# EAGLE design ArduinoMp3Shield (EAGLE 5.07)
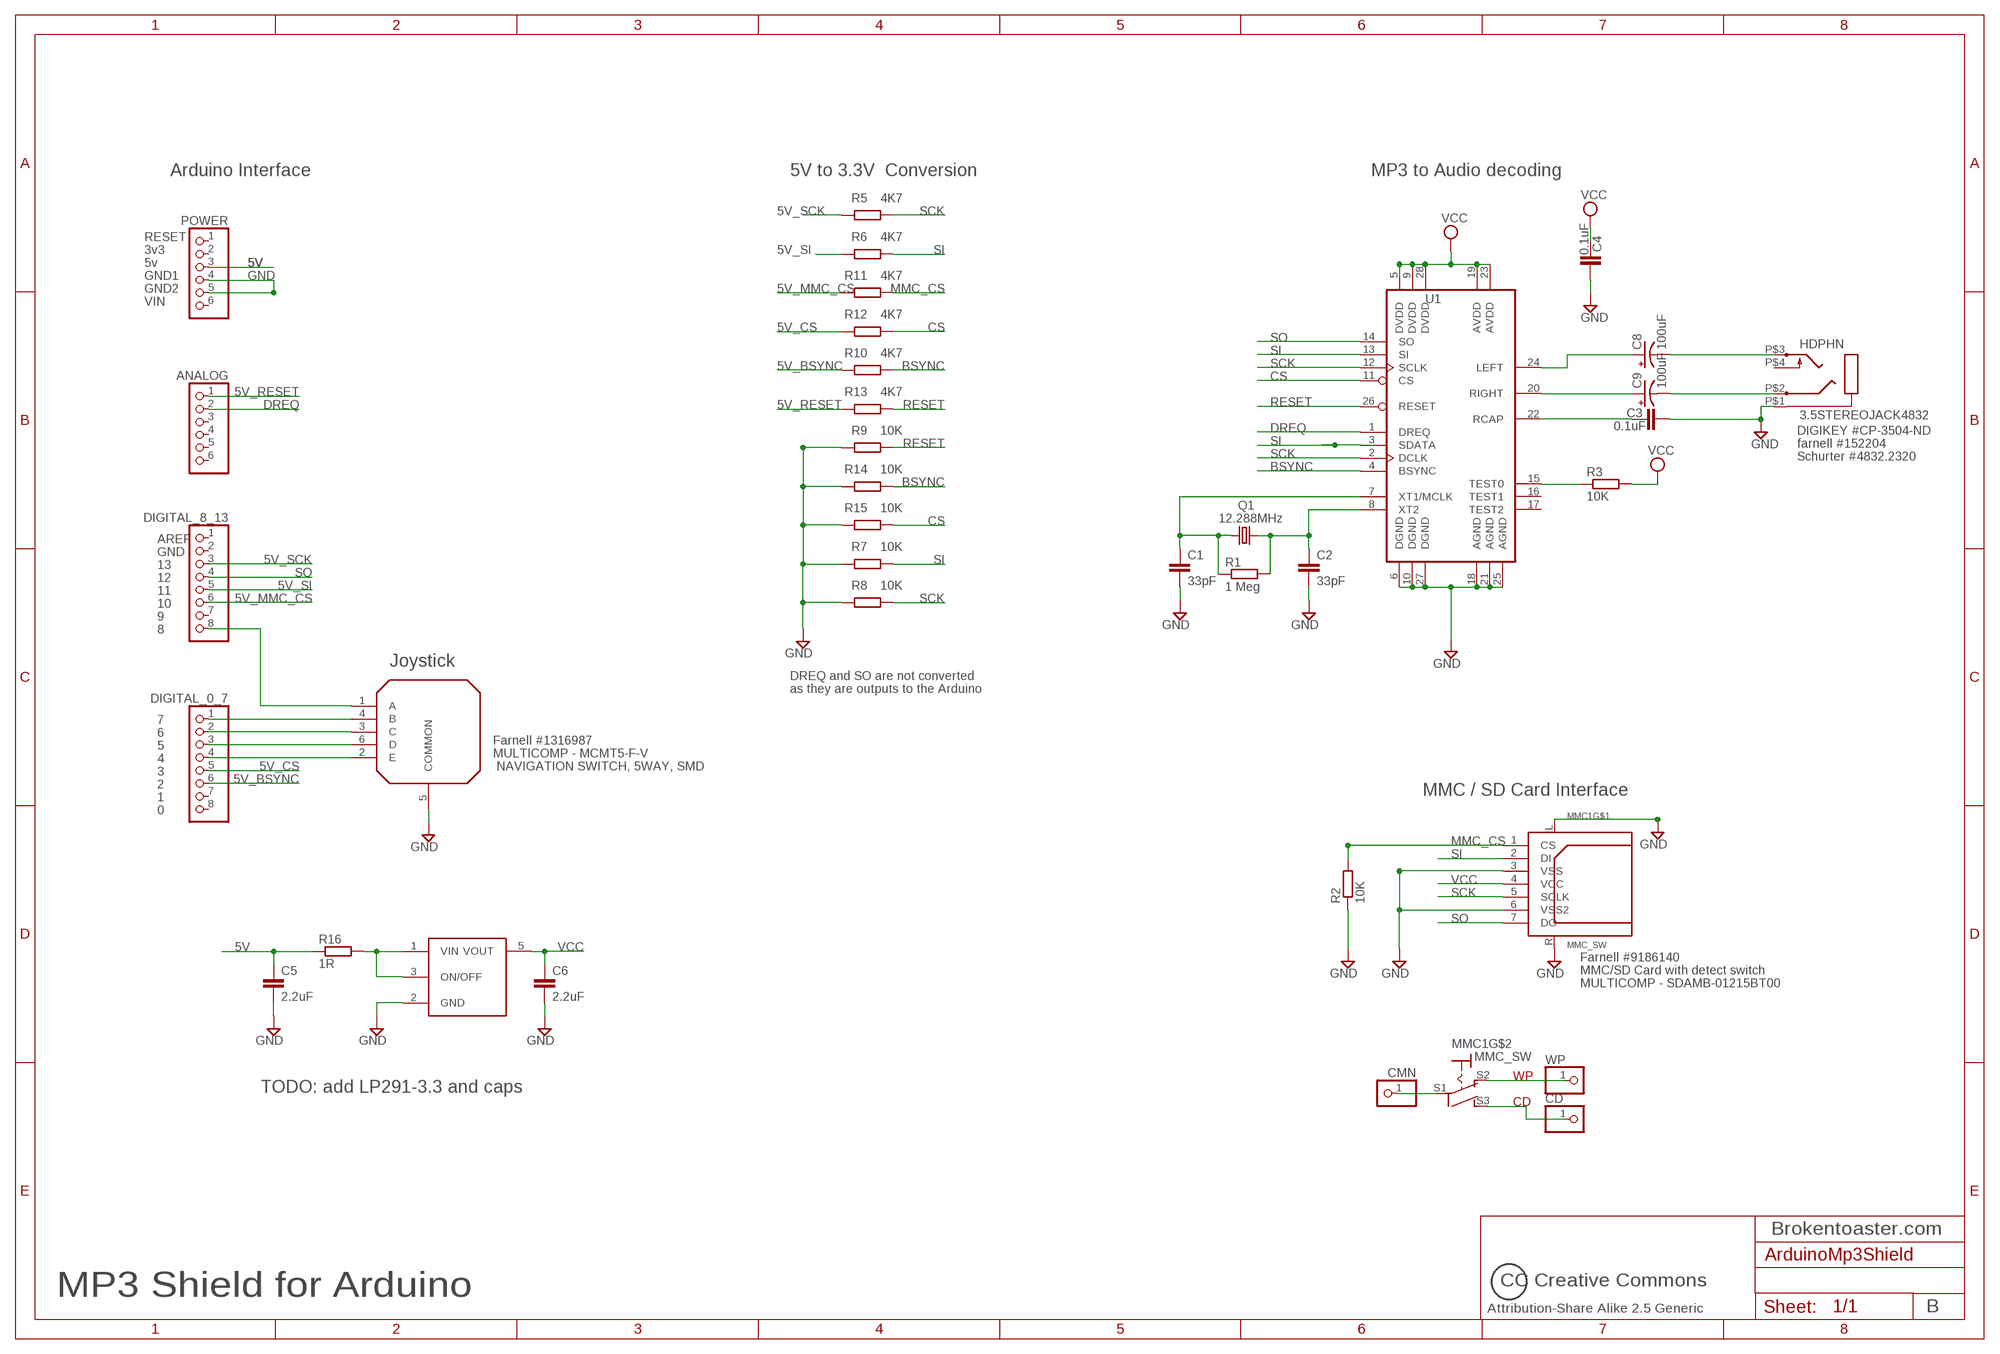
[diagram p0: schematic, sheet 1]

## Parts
ANALOG  1X06  [1X06]
C1  33pF  C-EUC0805K  [C0805K]
C2  33pF  C-EUC0805K  [C0805K]
C3  0.1uF  C-EUC0805K  [C0805K]
C4  0.1uF  C-EUC0805K  [C0805K]
C5  2.2uF  C-EUC0805K  [C0805K]
C6  2.2uF  C-EUC0805K  [C0805K]
C8  100uF  CPOL-USE2.5-6  [E2,5-6]
C9  100uF  CPOL-USE2.5-6  [E2,5-6]
CD  PINHD-1X1  [1X01]
CMN  PINHD-1X1  [1X01]
DIGITAL_0_7  1X08  [1X08]
DIGITAL_8_13  1X08  [1X08]
HDPHN  3.5STEREOJACK4832  [4832-2320]
MMC1  MMC_SW  [SDAMB-01215BT00]
POWER  1X06  [1X06]
Q1  12.288MHz  CRYSTALHC49UP  [HC49UP]
R1  1 Meg  R-EU_R0805  [R0805]
R2  10K  R-EU_R0805  [R0805]
R3  10K  R-EU_R0805  [R0805]
R5  4K7  R-EU_R0805  [R0805]
R6  4K7  R-EU_R0805  [R0805]
R7  10K  R-EU_R0805  [R0805]
R8  10K  R-EU_R0805  [R0805]
R9  10K  R-EU_R0805  [R0805]
R10  4K7  R-EU_R0805  [R0805]
R11  4K7  R-EU_R0805  [R0805]
R12  4K7  R-EU_R0805  [R0805]
R13  4K7  R-EU_R0805  [R0805]
R14  10K  R-EU_R0805  [R0805]
R15  10K  R-EU_R0805  [R0805]
R16  1R  R-EU_R0805  [R0805]
S1  MCMT5  [MCMT4]
U1  VS1001K  [SOIC-28]
U2  LP2981AIM-2.8  [MF05A]
WP  PINHD-1X1  [1X01]

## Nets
5V: C5.1 POWER.3 R16.1
5V_BSYNC: DIGITAL_0_7.6 R10.2
5V_CS: DIGITAL_0_7.5 R12.2
5V_MMC_CS: DIGITAL_8_13.6 R11.2
5V_RESET: ANALOG.1 R13.2
5V_SCK: DIGITAL_8_13.3 R5.2
5V_SI: DIGITAL_8_13.5 R6.1
BSYNC: R10.1 R14.1 U1.4(BSYNC)
CS: R12.1 R15.1 U1.11(CS)
DREQ: ANALOG.2 U1.1(DREQ)
GND: C1.2 C2.2 C3.2 C4.2 C5.2 C6.2 HDPHN.P$1 MMC1.3(VSS) MMC1.6(VSS2) MMC1.L MMC1.R POWER.4 POWER.5 R2.1 R7.2 R8.2 R9.2 R14.2 R15.2 S1.5(COMMON) U1.6(DGND) U1.10(DGND) U1.18(AGND) U1.21(AGND) U1.25(AGND) U1.27(DGND) U2.2(GND)
MMC_CS: MMC1.1(CS) R2.2 R11.1
N$1: R3.1 U1.15(TEST0)
N$2: C8.+ U1.24(LEFT)
N$3: C8.- HDPHN.P$3
N$4: C9.+ U1.20(RIGHT)
N$5: C9.- HDPHN.P$2
N$7: C3.1 U1.22(RCAP)
N$9: C1.1 Q1.1 R1.1 U1.7(XT1/MCLK)
N$10: C2.1 Q1.2 R1.2 U1.8(XT2)
N$11: DIGITAL_0_7.4 S1.2(E)
N$12: DIGITAL_0_7.3 S1.6(D)
N$14: DIGITAL_0_7.2 S1.3(C)
N$15: DIGITAL_0_7.1 S1.4(B)
N$16: DIGITAL_8_13.8 S1.1(A)
RESET: R9.1 R13.1 U1.26(RESET)
SCK: MMC1.5(SCLK) R5.1 R8.1 U1.2(DCLK) U1.12(SCLK)
SD_SW_CD: CD.1 MMC1.S3(S)
SD_SW_COMM: CMN.1 MMC1.S1(P)
SI: MMC1.2(DI) R6.2 R7.1 U1.3(SDATA) U1.13(SI)
SO: DIGITAL_8_13.4 MMC1.7(DO) U1.14(SO)
VBATT_IN: R16.2 U2.1(VIN) U2.3(ON/OFF)
VCC: C4.1 C6.1 MMC1.4(VCC) R3.2 U1.5(DVDD) U1.9(DVDD) U1.19(AVDD) U1.23(AVDD) U1.28(DVDD) U2.5(VOUT)
WP: MMC1.S2(O) WP.1
Unconnected: ANALOG.3 ANALOG.4 ANALOG.5 ANALOG.6 DIGITAL_0_7.7 DIGITAL_0_7.8 DIGITAL_8_13.1 DIGITAL_8_13.2 DIGITAL_8_13.7 HDPHN.P$4 POWER.1 POWER.2 POWER.6 U1.16(TEST1) U1.17(TEST2)

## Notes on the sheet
- Arduino Interface | 5V to 3.3V  Conversion | MP3 to Audio decoding
- RESET
- 3v3
- 5v
- GND1
- GND2
- VIN
- DIGIKEY #CP-3504-ND
- farnell #152204
- Schurter #4832.2320
- AREF
- GND
- 13
- 12
- 11
- 10
- 9
- 8
- Joystick
- DREQ and SO are not converted
- as they are outputs to the Arduino
- 7
- 6
- Farnell #1316987
- 5
- MULTICOMP - MCMT5-F-V
- 4
- NAVIGATION SWITCH, 5WAY, SMD
- 3
- 2
- MMC / SD Card Interface
- 1
- 0
- Farnell #9186140
- MMC/SD Card with detect switch
- MULTICOMP - SDAMB-01215BT00
- TODO: add LP291-3.3 and caps
- Brokentoaster.com
- CC Creative Commons
- MP3 Shield for Arduino
- Attribution-Share Alike 2.5 Generic | B

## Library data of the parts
ANALOG POWER = arduino:1X06: PIN HEADER
C1-C6 = rcl:C-EU: CAPACITOR, European symbol
C8 C9 = ButterflyMP3:CPOL-US: POLARIZED CAPACITOR, American symbol
CD CMN WP = pinhead:PINHD-1X1: PIN HEADER
DIGITAL_0_7 DIGITAL_8_13 = arduino:1X08: PIN HEADER
HDPHN = ButterflyMP3:3.5STEREOJACK: 3.5mm Stero Jack Standard through hole headphone socket. farnell #152204
MMC1 = ButterflyMP3:MMC_SW
Q1 = crystal:CRYSTAL: CRYSTAL
R1-R3 R5-R16 = ButterflyMP3:R-EU_: RESISTOR, European symbol
S1 = Switch:MCMT5
U1 = ButterflyMP3:VS1001K
U2 = ButterflyMP3:LP2981AIM-2.8: 2.8V LDO

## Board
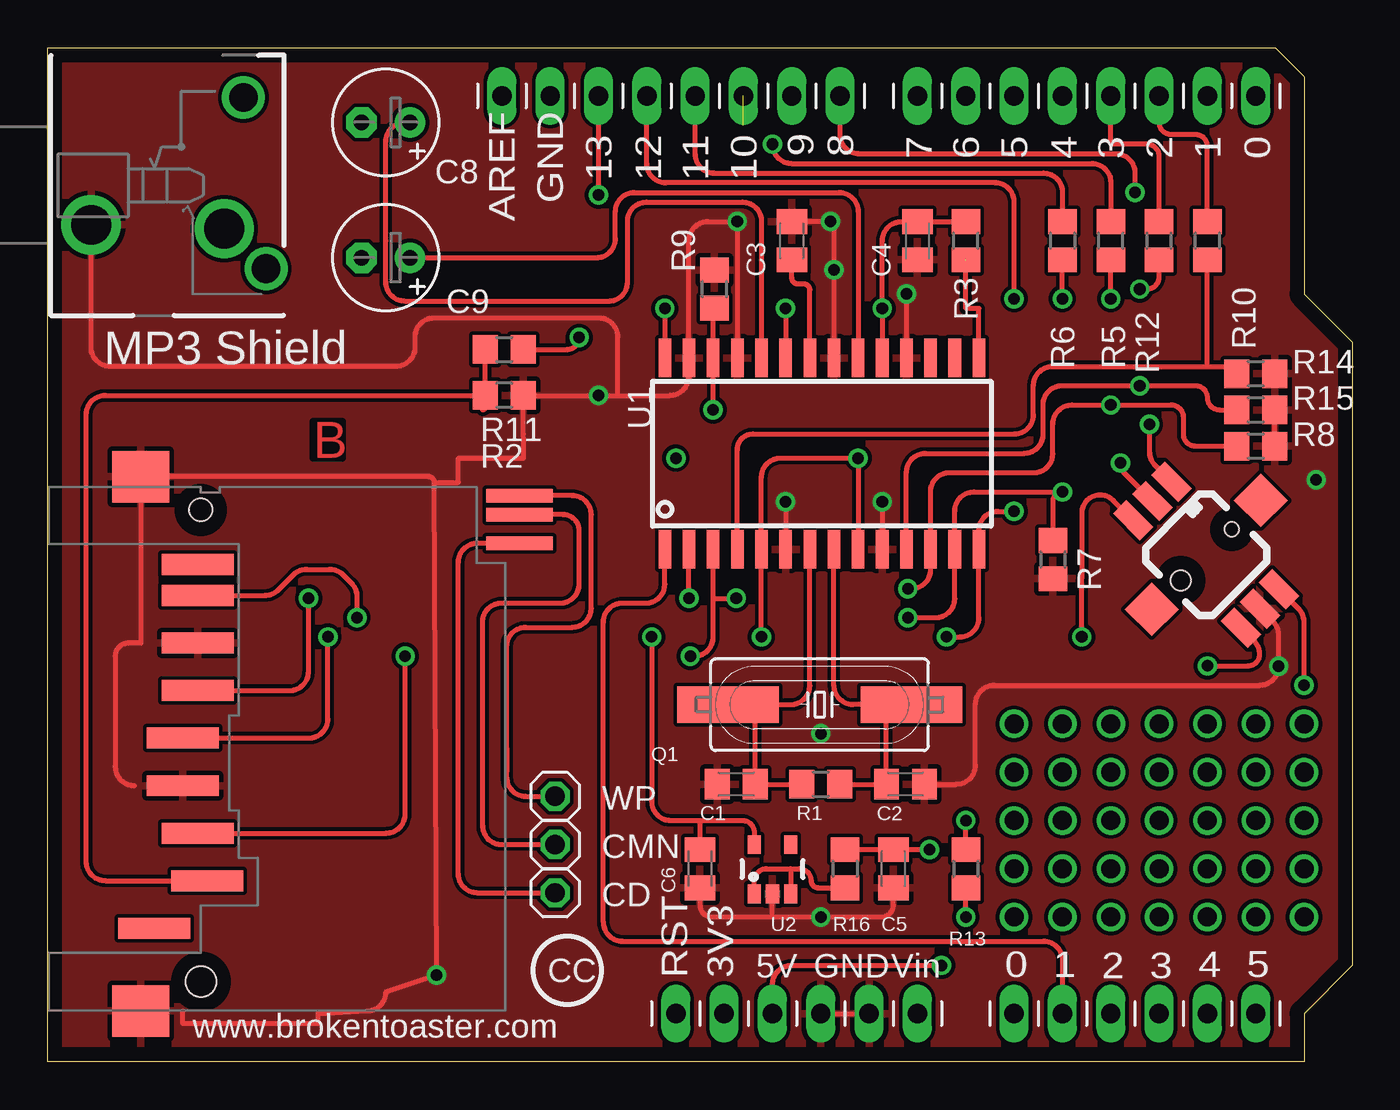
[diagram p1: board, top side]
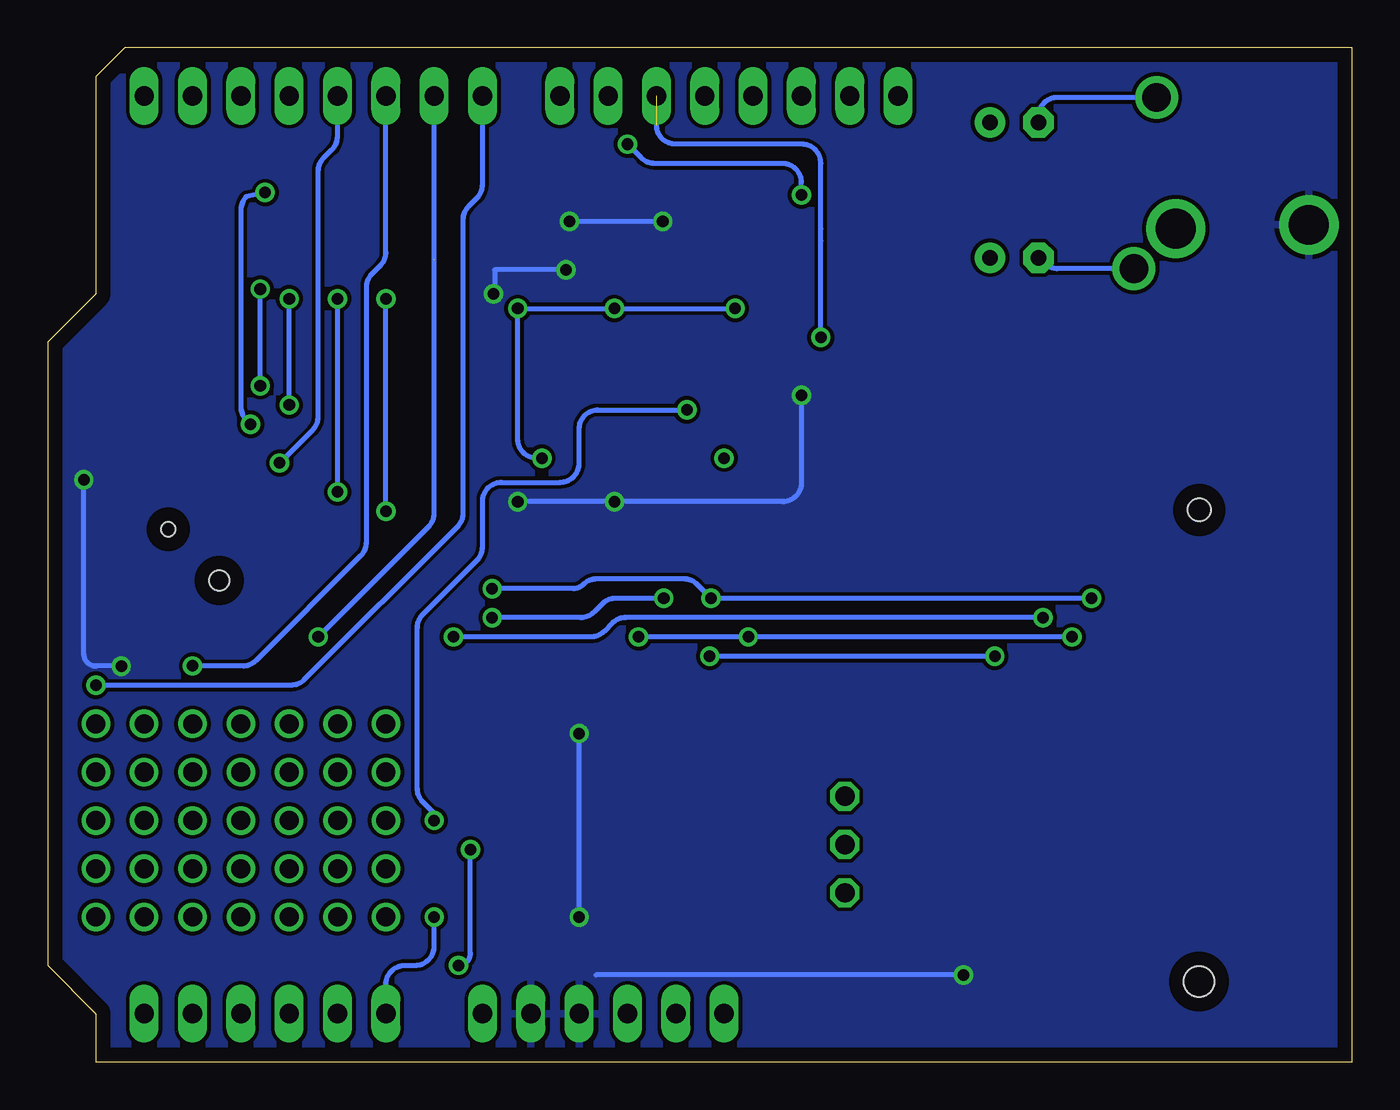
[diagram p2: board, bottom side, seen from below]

Size 68.58 x 53.34 mm. Coordinates in mm from the lower left corner, seen from the top.
Outline: 0,53.34 64.52,53.34 66.04,51.82 66.04,40.39 68.58,37.85 68.58,5.08 66.04,2.54 66.04,0 0,0 0,53.34
Copper layers (1*16): Top 0.035mm / dielectric 1.5mm / Bottom 0.035mm
Design rules "default *": minimum track width 10mil, minimum drill 24mil, track to track 8mil, track to pad 8mil, pad to pad 8mil, via to via 8mil, smd to smd 8mil, copper to edge 30mil, drill to drill 8mil, minimum pad ring 10mil, minimum via ring 8mil, stop-mask expansion 4mil, vias tented up to drill 0mil, thermal gap 10mil

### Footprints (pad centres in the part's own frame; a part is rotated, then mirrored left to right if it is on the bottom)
1X06 = drill 1.016 long: 1 -6.35,0; 2 -3.81,0; 3 -1.27,0; 4 1.27,0; 5 3.81,0; 6 6.35,0
C0805K = smd 1.3 x 1.6: 1 -1,0; 2 1,0
E2,5-6 = drill 0.813 pad 1.6 round: + -1.27,0 | drill 0.813 pad 1.6 octagon: - 1.27,0
1X01 = drill 1.016 octagon: 1 0,0
1X08 = drill 1.016 long: 1 -8.89,0; 2 -6.35,0; 3 -3.81,0; 4 -1.27,0; 5 1.27,0; 6 3.81,0; 7 6.35,0; 8 8.89,0
4832-2320 = drill 2.1 round: P$1 2.5,-2.2; P$4 9.5,-2.4 | drill 1.5 round: P$2 11.7,-4.5; P$3 10.5,4.5
SDAMB-01215BT00 = smd 1.1 x 3.79: 1 -5.3,0.345; 2 -7.8,-0.155; 3 -10.3,-0.955; 4 -12.8,-0.955; 5 -15.3,-0.155; 6 -17.8,-0.155; 7 -20.3,-0.155; 8 -21.925,-0.155; 9 -2.8,-2.455 | smd 2.7 x 3: L -26.55,-3.15; R 1.55,-3.15 | smd 0.7 x 3.5: S1 -24.55,16.75; S2 -25.55,16.75; S3 -23.05,16.75 | hole 1.6: 0,0 | hole 1.2: -24.8,0
HC49UP = smd 5.334 x 1.93: 1 -4.826,0; 2 4.826,0
R0805 = smd 1.3 x 1.5: 1 -1,0; 2 1,0
MCMT4 = smd 2 x 1: 1 -4,1.425; 2 -4,0; 3 -4,-1.425; 4 4,1.425; 5 4,0; 6 4,-1.425 | smd 2 x 2: NC1 0,4.05; NC2 0,-4.05 | hole 0.75: 0,1.9 | hole 1.05: 0,-1.9
SOIC-28 = smd 0.66 x 2.032: 1 -6.985,-5.029; 2 -5.715,-5.029; 3 -4.445,-5.029; 4 -3.175,-5.029; 5 -1.905,-5.029; 6 -0.635,-5.029; 7 0.635,-5.029; 8 1.905,-5.029; 9 3.175,-5.029; 10 4.445,-5.029; 11 5.715,-5.029; 12 6.985,-5.029; 13 8.255,-5.029; 14 9.525,-5.029; 15 9.525,5.029; 16 8.255,5.029; 17 6.985,5.029; 18 5.715,5.029; 19 4.445,5.029; 20 3.175,5.029; 21 1.905,5.029; 22 0.635,5.029; 23 -0.635,5.029; 24 -1.905,5.029; 25 -3.175,5.029; 26 -4.445,5.029; 27 -5.715,5.029; 28 -6.985,5.029
MF05A = smd 0.69 x 0.99: 1 -0.95,-2.59; 2 0,-2.59; 3 0.95,-2.59; 4 0.95,0; 5 -0.95,0

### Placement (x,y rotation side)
ANALOG  57.15,2.54 0 top
C1  36.2,14.61 180 top
C2  45.09,14.61 0 top
C3  39.12,43.18 90 top
C4  45.72,43.18 270 top
C5  44.45,10.16 270 top
C6  34.29,10.16 270 top
C8  17.78,49.4 180 top
C9  17.78,42.29 180 top
CD  26.67,8.89 0 top
CMN  26.67,11.43 0 top
DIGITAL_0_7  54.61,50.8 0 top
DIGITAL_8_13  32.77,50.8 0 top
HDPHN  -0.21,46.22 0 top
MMC1  8.05,4.23 270 top
POWER  39.37,2.54 0 top
Q1  40.58,18.79 0 top
R1  40.64,14.61 0 top
R2  24,35.05 180 top
R3  48.26,43.18 90 top
R5  55.88,43.18 90 top
R6  53.34,43.18 270 top
R7  52.83,26.42 270 top
R8  63.5,32.38 0 top
R9  35.05,40.64 90 top
R10  60.96,43.18 90 top
R11  24,37.47 0 top
R12  58.42,43.18 90 top
R13  48.26,10.16 270 top
R14  63.5,36.2 0 top
R15  63.5,34.29 0 top
R16  41.91,10.16 270 top
S1  60.89,26.67 315 top
U1  39.42,31.99 0 top
U2  38.1,11.43 0 top
WP  26.67,13.97 0 top

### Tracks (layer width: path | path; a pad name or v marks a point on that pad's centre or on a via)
5V  (via drill 0.61)
  Top 0.254: C5.1 R16.1 C5.1 | C5.1 v46.35,11.16 C5.1 | POWER.3 38.1,4.08 arc-90 39.1,5.08 v46.99,5.08
  Bottom 0.254: v46.99,5.08 arc-90 46.35,5.71 v46.35,11.16
5V_BSYNC
  Top 0.254: DIGITAL_0_7.6 58.42,49.4 arc90 59.05,48.77 60.33,48.77 arc-90 60.96,48.13 R10.2
5V_CS
  Top 0.254: DIGITAL_0_7.5 55.88,48.26 57.78,48.26 arc-90 58.42,47.62 R12.2
5V_MMC_CS  (via drill 0.61)  (1 unrouted)
  Top 0.254: R11.2 27.3,37.47 arc90 v27.94,38.1
  Bottom 0.254: v27.94,38.1 27.94,43.18 | 27.94,43.18 27.94,43.81 | 27.94,43.18 27.94,47.26 arc-90 28.94,48.26 35.58,48.26 arc90 36.58,49.26
5V_RESET  (via drill 0.61)
  Top 0.254: v48.26,7.62 R13.2
  Bottom 0.254: ANALOG.1 50.8,4.08 arc90 49.8,5.08 49.26,5.08 arc-90 48.26,6.08 v48.26,7.62
5V_SCK  (via drill 0.61)
  Top 0.254: v28.96,45.59 DIGITAL_8_13.3 | v38.1,48.26 38.1,48.24 arc90 39.1,47.24 54.88,47.24 arc-90 55.88,46.24 R5.2
  Bottom 0.254: v28.96,45.59 28.96,46.24 arc-90 29.96,47.24 36.67,47.24 arc45 37.38,47.54 v38.1,48.26
5V_SI
  Top 0.254: DIGITAL_8_13.5 34.04,47.74 arc90 35.04,46.74 52.34,46.74 arc-90 53.34,45.74 R6.1
BSYNC
  Top 0.254: 60.96,36.58 52.82,36.58 arc90 51.82,35.58 51.82,34.02 arc-90 50.82,33.02 37.07,33.02 arc90 36.25,32.2 U1.4 | 60.96,36.58 62.12,36.58 | R14.1 62.21,36.48 arc45 61.99,36.58 60.96,36.58 | 60.96,36.58 R10.1
CS  (via drill 0.61)
  Top 0.254: U1.11 45.14,31 arc-90 46.14,32 51.32,32 arc90 52.32,33 52.32,34.56 arc-90 53.32,35.56 v57.4,35.56 60.33,35.56 arc-90 60.96,34.92 arc90 61.59,34.29 R15.1 | R12.1 58.42,41.27 arc-90 57.78,40.64 v57.4,40.64
  Bottom 0.254: v57.4,35.56 v57.4,40.64
DREQ
  Top 0.254: ANALOG.2 53.34,5.35 arc90 52.34,6.35 30.21,6.35 arc-90 29.21,7.35 29.21,23.13 arc-90 30.21,24.13 31.44,24.13 arc90 32.44,25.13 U1.1
GND  (via drill 0.61)
  Top 0.254: U1.25 v36.25,44.2 34.71,44.2 arc90 33.71,43.2 U1.27 33.71,36.05 arc-90 32.71,35.05 29.97,35.05 | U1.21 v41.33,41.66 41.33,44.2 v41.15,44.2 39.12,44.2 C3.2 | HDPHN.P$1 2.29,37.58 arc90 3.29,36.58 18.3,36.58 arc90 19.3,37.58 19.3,38.12 arc-90 20.3,39.12 28.97,39.12 arc-90 29.97,38.12 29.97,35.05 | 29.97,35.05 v28.96,35.05 R2.1 25,33.02 25.02,32.77 25.02,31.75 21.59,31.75 21.59,30.48 20.32,30.48 | 4.56,14.53 arc-90 3.56,15.53 3.56,21.34 arc-90 4.25,22.03 4.91,22.03 4.91,30.48 arc-3 MMC1.L 20.02,30.78 arc-90 20.32,30.48 | 7.11,2.68 7.11,2.03 14.22,2.03 14.22,2.54 16.78,2.68 arc90 17.78,3.68 v20.45,4.57 20.32,30.48 | v45.14,40.39 U1.18 | v43.87,29.46 U1.10 | v38.79,29.46 U1.6 | C1.2 35.2,13.95 | C2.2 47.77,14.61 arc90 48.77,15.61 48.77,18.81 arc-90 49.77,19.81 63.7,19.81 arc90 v64.7,20.81 64.7,22.45 arc45 64.41,23.15 | POWER.4 POWER.5 | R8.2 64.5,34.02 arc-90 64.77,34.29 | C6.2 34.29,8.26 arc90 34.92,7.62 38.1,7.62 | 38.1,7.62 U2.2 | C5.2 44.45,8.26 arc-90 43.81,7.62 40.39,7.62 38.1,7.62
  Bottom 0.254: v36.25,44.2 v41.15,44.2 | v41.33,41.66 45.09,41.66 45.09,40.39 v45.14,40.39 | v43.87,29.46 v38.79,29.46 29.96,29.46 arc-90 28.96,30.46 v28.96,35.05 | v20.45,4.57 39.77,4.57 | v66.67,30.61 66.67,21.45 arc-90 66.04,20.81 v64.7,20.81 | v40.64,7.62 v40.64,17.27
  pour Bottom: -2.54,55.88 71.12,55.88 71.12,0 -2.54,0
  pour Top: -5.08,53.34 68.58,53.34 68.58,0 -5.08,0
MMC_CS
  Top 0.254: MMC1.1 3.03,9.53 arc-90 2.03,10.53 2.03,34.05 arc-90 3.03,35.05 R2.2 arc90 22.86,34.91 22.86,34.29 arc90 23,34.43 R11.1
N$1  (1 unrouted)
  Top 0.254: U1.15 48.95,39.62 48.26,39.62 48.26,42.16
N$2
  Top 0.254: U1.24 37.52,44.21 arc90 36.52,45.21 31.48,45.21 arc90 30.48,44.21 30.48,41.91 30.48,41.01 arc-90 29.48,40.01 18.78,40.01 arc-90 17.78,41.01 17.78,43.18 17.78,48.4 arc-90 18.78,49.4 C8.+
N$3
  Bottom 0.254: HDPHN.P$3 15.51,50.72 arc-90 16.51,49.72 C8.-
N$4
  Top 0.254: U1.20 42.6,44.72 arc90 41.6,45.72 30.84,45.72 arc90 29.84,44.72 29.84,43.29 arc-90 28.84,42.29 C9.+
N$5
  Bottom 0.254: HDPHN.P$2 15.52,41.72 arc45 16.23,42.01 C9.-
N$7
  Top 0.254: U1.22 40.06,40.59 arc90 39.74,40.91 39.43,40.91 arc-90 39.12,41.23 C3.1
N$9
  Top 0.254: U1.7 40.06,19.8 arc-90 39.06,18.8 36.58,18.8 36.58,18.79 | 36.58,18.79 Q1.1 | 36.58,18.79 37.2,18.79 C1.1 R1.1
N$10
  Top 0.254: Q1.2 44.7,18.8 | 44.7,18.8 42.33,18.8 arc-90 41.33,19.8 U1.8 | 44.7,18.8 44.09,18.8 C2.1 R1.2
N$11  (via drill 0.61)
  Top 0.254: S1.2 56.62,30.95 arc-45 v56.39,31.5
  Bottom 0.254: v56.39,31.5 54.65,33.23 arc-45 54.36,33.94 54.36,46.83 arc45 54.06,47.54 53.63,47.97 arc-45 53.34,48.67 DIGITAL_0_7.4
N$12  (via drill 0.61)
  Top 0.254: S1.6 63.41,22.14 arc-45 63.7,21.43 arc-90 63.1,20.83 v60.96,20.83
  Bottom 0.254: v60.96,20.83 58.33,20.83 arc-45 57.62,21.12 52.11,26.63 arc-45 51.82,27.34 51.82,40.73 arc45 51.52,41.44 51.09,41.87 arc-45 50.8,42.58 DIGITAL_0_7.3
N$14  (via drill 0.61)
  Top 0.254: v54.36,22.35 54.37,28.45 54.37,28.88 arc-90 55.31,29.82 arc-45 56.02,29.53 S1.3
  Bottom 0.254: v54.36,22.35 48.55,28.16 arc-45 48.26,28.86 DIGITAL_0_7.2
N$15  (via drill 0.61)
  Top 0.254: v66.04,19.81 66.04,23.12 arc45 65.75,23.83 S1.4
  Bottom 0.254: v66.04,19.81 55.79,19.81 arc-45 55.08,20.11 47.03,28.16 arc-45 46.74,28.86 46.74,44.29 arc45 46.44,45 46.01,45.43 arc-45 45.72,46.13 DIGITAL_0_7.1
N$16  (via drill 0.61)
  Top 0.254: S1.1 58.2,31.37 arc-45 57.91,32.08 v57.91,33.53 | DIGITAL_8_13.8 41.66,48.75 arc90 42.66,47.75 56.15,47.75 arc-90 57.15,46.75 v57.15,45.72
  Bottom 0.254: v57.91,33.53 58.13,33.74 arc45 58.42,34.45 58.42,44.8 arc45 58.13,45.51 v57.15,45.72
N$17  (via drill 1)
  other vias: 50.8,7.62
N$18  (via drill 1)
  other vias: 66.04,7.62
N$19  (via drill 1)
  other vias: 63.5,7.62
N$20  (via drill 1)
  other vias: 60.96,7.62
N$21  (via drill 1)
  other vias: 58.42,7.62
N$22  (via drill 1)
  other vias: 55.88,7.62
N$23  (via drill 1)
  other vias: 55.88,10.16
N$24  (via drill 1)
  other vias: 58.42,10.16
N$25  (via drill 1)
  other vias: 60.96,10.16
N$26  (via drill 1)
  other vias: 63.5,10.16
N$27  (via drill 1)
  other vias: 66.04,10.16
N$28  (via drill 1)
  other vias: 66.04,12.7
N$29  (via drill 1)
  other vias: 60.96,12.7
N$30  (via drill 1)
  other vias: 63.5,12.7
N$31  (via drill 1)
  other vias: 58.42,12.7
N$32  (via drill 1)
  other vias: 55.88,12.7
N$33  (via drill 1)
  other vias: 53.34,12.7
N$34  (via drill 1)
  other vias: 53.34,10.16
N$35  (via drill 1)
  other vias: 50.8,10.16
N$36  (via drill 1)
  other vias: 50.8,12.7
N$37  (via drill 1)
  other vias: 50.8,15.24
N$38  (via drill 1)
  other vias: 53.34,15.24
N$39  (via drill 1)
  other vias: 55.88,15.24
N$40  (via drill 1)
  other vias: 58.42,15.24
N$41  (via drill 1)
  other vias: 60.96,15.24
N$42  (via drill 1)
  other vias: 63.5,15.24
N$43  (via drill 1)
  other vias: 66.04,15.24
N$44  (via drill 1)
  other vias: 66.04,17.78
N$45  (via drill 1)
  other vias: 63.5,17.78
N$46  (via drill 1)
  other vias: 60.96,17.78
N$47  (via drill 1)
  other vias: 58.42,17.78
N$48  (via drill 1)
  other vias: 55.88,17.78
N$49  (via drill 1)
  other vias: 53.34,17.78
N$50  (via drill 1)
  other vias: 50.8,17.78
N$51  (via drill 0.61)
  other vias: 33.02,31.75
N$52  (via drill 1)
  other vias: 53.34,7.62
RESET  (via drill 0.61)
  Top 0.254: R9.1 34.98,39.64 U1.26 v34.98,34.29 | R13.1 v48.26,12.7
  Bottom 0.254: v34.98,34.29 39.64,34.29 arc-90 40.64,33.29 40.64,31.48 arc90 41.64,30.48 44.72,30.48 arc-90 45.72,29.48 45.72,27.08 arc45 46.01,26.38 48.86,23.53 arc-45 49.15,22.83 49.15,14.38 arc-45 48.86,13.68 48.26,13.08 v48.26,12.7
SCK  (via drill 0.61)
  Top 0.254: v55.88,40.13 R5.1 | v13.72,24.38 13.72,20.53 arc-90 12.72,19.53 MMC1.5 | v45.21,24.89 45.41,24.89 arc90 46.41,25.89 U1.12 46.41,29.99 arc-90 47.41,30.99 51.83,30.99 arc90 52.83,31.99 52.83,33.54 arc-90 53.83,34.54 v55.88,34.54 59.05,34.54 arc-90 59.69,33.91 59.69,33.02 arc90 60.33,32.38 R8.1 | v33.71,24.38 U1.2
  Bottom 0.254: v55.88,34.54 v55.88,40.13 | v13.72,24.38 v33.71,24.38 34.43,25.11 arc-45 35.14,25.4 39.72,25.4 arc-45 40.42,25.11 arc45 40.94,24.89 v45.21,24.89
SD_SW_CD
  Top 0.254: MMC1.S3 22.59,27.28 arc90 21.59,26.28 21.59,9.89 arc90 22.59,8.89 CD.1
SD_SW_COMM
  Top 0.254: CMN.1 23.86,11.43 arc-90 22.86,12.43 22.86,23.13 arc-90 23.86,24.13 26.94,24.13 arc90 27.94,25.13 27.94,27.94 arc90 27.1,28.78 MMC1.S1
SI  (via drill 0.61)
  Top 0.254: v53.34,40.13 R6.2 | v18.8,21.34 18.8,13.03 arc-90 17.8,12.03 MMC1.2 | 34.98,24.38 U1.3 | v33.78,21.34 33.98,21.34 arc90 34.98,22.34 34.98,24.38 | v45.21,23.37 46.68,23.37 arc90 47.68,24.37 U1.13 47.68,28.97 arc-90 48.68,29.97 v53.34,29.97 arc90 52.83,29.46 R7.1 | 34.98,24.38 v36.2,24.38
  Bottom 0.254: v53.34,29.97 v53.34,40.13 | v18.8,21.34 v33.78,21.34 | v36.2,24.38 38.72,24.38 arc-45 39.42,24.09 39.85,23.66 arc45 40.56,23.37 v45.21,23.37
SO  (via drill 0.61)
  Top 0.254: v50.8,28.96 49.95,28.96 arc90 48.95,27.96 U1.14 48.95,23.35 arc-90 47.95,22.35 v47.24,22.35 | v16.26,23.37 16.26,24.48 arc45 15.96,25.18 15.53,25.61 arc45 14.83,25.91 13.62,25.91 arc45 12.91,25.61 12.12,24.82 arc-45 11.42,24.53 MMC1.7 | DIGITAL_8_13.4 31.5,47.23 arc90 32.5,46.23 49.8,46.23 arc-90 50.8,45.23 v50.8,40.13
  Bottom 0.254: v50.8,28.96 v50.8,40.13 | v47.24,22.35 40.04,22.35 arc-45 39.33,22.64 38.9,23.07 arc45 38.19,23.37 v16.26,23.37
VBATT_IN
  Top 0.254: 39.05,10.16 U2.3 | U2.1 37.15,9.53 arc-90 37.78,10.16 39.05,10.16 | 39.05,10.16 39.5,10.16 arc-90 40.13,9.53 arc90 40.5,9.16 R16.2
VCC  (via drill 0.61)
  Top 0.254: v14.73,22.35 14.73,18.03 arc-90 13.73,17.03 MMC1.4 | v37.52,22.35 U1.5 37.52,30.75 arc-90 38.52,31.75 v42.6,31.75 U1.9 | U1.19 v43.87,39.62 43.87,43.18 arc-90 44.87,44.18 C4.1 R3.2 | v32.44,39.62 U1.28 | v38.79,39.62 U1.23 | v31.75,22.35 31.75,13.7 arc90 32.75,12.7 34.29,12.7 | 34.29,12.7 36.52,12.7 arc-90 37.15,12.06 U2.5 | 34.29,12.7 C6.1
  Bottom 0.254: v14.73,22.35 v31.75,22.35 v37.52,22.35 | v32.44,39.62 v38.79,39.62 v43.87,39.62 43.87,32.75 arc-90 42.87,31.75 v42.6,31.75
WP
  Top 0.254: MMC1.S2 27.57,29.78 arc-90 28.57,28.78 28.57,23.86 arc-90 27.57,22.86 25.13,22.86 arc90 24.13,21.86 24.13,16.51 | 24.13,16.51 24.13,15.24 | WP.1 25.13,13.97 arc-90 24.13,14.97 24.13,16.51

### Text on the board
Top: B
tPlace: MP3 Shield | CC | www.brokentoaster.com
tNames: 9 | 8 | 7 | 6 | 5 | 4 | 3 | 2 | 1 | 0 | 13 | 12 | 11 | 10 | GND | AREF | RST | 3V3 | 5V | GND | Vin | 0 | 1 | 2 | 3 | 4 | 5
